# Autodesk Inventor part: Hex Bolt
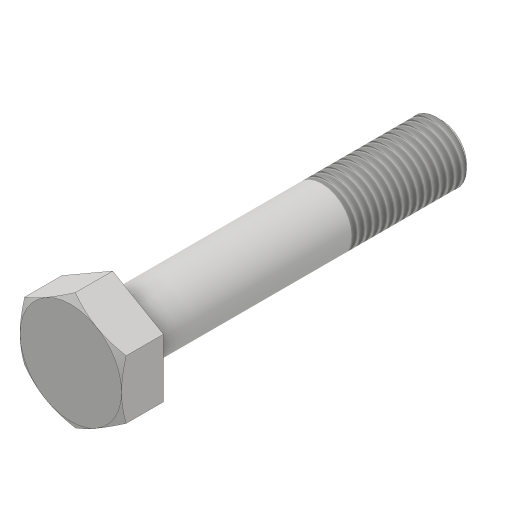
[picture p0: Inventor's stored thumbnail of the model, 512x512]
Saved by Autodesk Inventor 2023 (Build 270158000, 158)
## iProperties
Created: 2016-05
Part Number: Hex Bolt
Material: Generic
Document SubType Name: Modeling
Designer: CADCIM
Density: 1 g/cm^3
Appearance: Default
Author: CADCIM
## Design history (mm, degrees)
sketch "Sketch1"
  geometry: L1 (0, -19.63)-(-17, -9.815); L2 (-17, -9.815)-(-17, 9.815); L3 (-17, 9.815)-(0, 19.63); L4 (0, 19.63)-(17, 9.815); L5 (17, 9.815)-(17, -9.815); L6 (17, -9.815)-(0, -19.63); 2 further points
  constraints: 12 end point, 1 coincident, 13 other
  dimensions: "d0" = 34 distance between parallel lines of L2 L5
extrude "Extrusion1" new body sketch "Sketch1" distance "d1" = 14; taper "d2" = 0 deg
sketch "Sketch2"
  geometry: 1 further point
sketch "Sketch3"
  geometry: C1 r 10 at (0, 0); 1 further point
  constraints: 1 centre point, 1 coincident
  dimensions: "d3" = 20 diameter of C1
extrude "Extrusion2" join sketch "Sketch3" distance "d4" = 110; taper "d5" = 0 deg
thread "Thread1" dims "d6" = 40, "d7" = 0
sketch "Sketch4"
  geometry: L1 (0, -19.63)-(17, -9.815) reference; C1 r 17 at (0, 0); 1 further point
  constraints: 1 centre point, 1 coincident, 1 tangent
extrude "Extrusion3" sketch "Sketch4" distance "d8" = 200; taper "d9" = 60 deg
chamfer "Chamfer1" distance "d10" = 1.5; stored, may be unused: second distance "d11" = 2, angle "d12" = 45 deg
body "Solid1"
